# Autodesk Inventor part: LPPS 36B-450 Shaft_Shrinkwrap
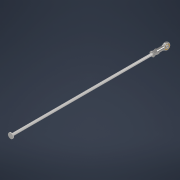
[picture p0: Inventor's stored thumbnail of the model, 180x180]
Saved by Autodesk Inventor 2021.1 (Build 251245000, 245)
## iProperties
Created: 2020-09
Part Number: LPPS 36B-450 Shaft_Shrinkwrap
Material: Generic
Document SubType Name: Modeling
Designer: J. Nielson
Density: 1 g/cm^3
Appearance: Default
Author: J. Nielson
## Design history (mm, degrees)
derived "LPPS 36B-450.iam"
body "Solid1"
node "LPPS-36B-450 ROD.ipt:1"
node "Custom Flanged Nut.ipt:1"
body "Solid2"
node "FEMALE Rod End SW.ipt:1"
body "Solid3"
node "JIS B 1181 - M8x1(4).ipt:1"
body "Solid4"
